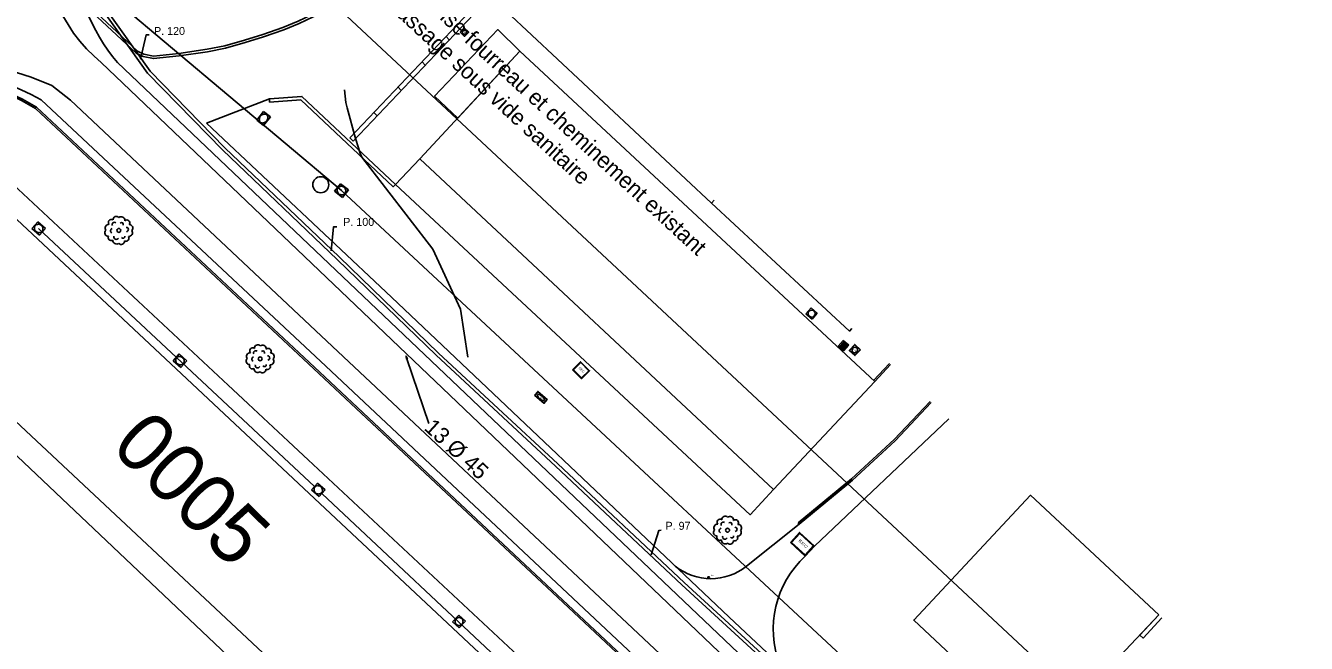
# Model space of a CAD drawing. Extents: x 343997 to 344255, y 298512 to 298767.
# Drawn here: x 344175.3 to 344255.3, y 298632.9 to 298671.5 of the extents above; entities that cross this region are included whole.
import ezdxf

# ---------------------------------------------------------------- set-up
doc = ezdxf.new("R2010")
doc.units = 0
for name, color, linetype in [('Commentaires', 7, 'Continuous'), ('Default', 7, 'Continuous'), ('DH_CADRE -CARTOUCHE', 7, 'Continuous'), ('DH_CADRE-CARTOUCHE', 7, 'Continuous'), ('DH_CADRE-CARTOUCHE-NORD', 7, 'Continuous'), ('DH_TEXTE', 7, 'Continuous'), ('DIR-Projet VRD1', 7, 'Continuous'), ('EL-FOURR', 7, 'Continuous'), ('GO_DALLE', 7, 'Continuous'), ('GO_MUR', 7, 'Continuous'), ('MT-DONNEE', 7, 'Continuous'), ('O-Projet New VRD', 7, 'Continuous'), ('PC_REBAR', 7, 'Continuous'), ('PS_MID', 7, 'Continuous'), ('PS_OBJECT', 7, 'Continuous'), ('PS_PLATE', 7, 'Continuous'), ('RES_EAU', 7, 'Continuous'), ('RES_EAU PLUVIALE', 7, 'Continuous'), ('RES_ELECTRICITE', 7, 'Continuous'), ('RES_MOYENNE TENSION', 7, 'Continuous')]:
    doc.layers.add(name, color=color, linetype=linetype)

# ---------------------------------------------------------------- blocks, each defined once
blk = doc.blocks.new('REG_INC')
at = {"layer": 'Default'}
for p, q in [((0, 0.1), (0.1, 0.1)), ((0, 0), (0, 0.1)), ((0.1, 0), (0, 0)), ((0.1, 0.1), (0.1, 0))]:
    blk.add_line(p, q, dxfattribs=at)
for start, end in [(135.0055, 180.0055), (180.0066, 225.0066), (90.0058, 135.0058), (225.0069, 270.0069), (45.0069, 90.0069), (270.0058, 315.0058), (0.0066, 45.0066), (315.0055, 0.0055)]:
    blk.add_arc((0.05, 0.05), 0.044, start, end, dxfattribs=at)
blk = doc.blocks.new('R5')
at = {"layer": 'Default'}
for p, q in [((0, 0.1), (0, 0)), ((0.1, 0.1), (0, 0.1)), ((0.02, 0.1), (0.02, 0)), ((0.04, 0.1), (0.04, 0)), ((0.06, 0.1), (0.06, 0)), ((0.08, 0.1), (0.08, 0)), ((0.1, 0), (0.1, 0.1)), ((0, 0), (0.1, 0)), ((0.06, 0), (0.06, 0))]:
    blk.add_line(p, q, dxfattribs=at)
blk = doc.blocks.new('RES_EAU')
at = {"layer": 'RES_EAU'}
for points in [[(0, 0), (0, 0.1), (0.1, 0.1), (0.1, 0)], [(0.003, 0.003), (0.003, 0.097), (0.097, 0.097), (0.097, 0.003)]]:
    blk.add_lwpolyline(points, close=True, dxfattribs=at)
blk.add_circle((0.05, 0.05), 0.035, dxfattribs=at)
blk.add_text('AEP', height=0.02, dxfattribs=at).set_placement((0.022, 0.045))
blk = doc.blocks.new('RES_ELECTRICITE')
at = {"layer": 'RES_ELECTRICITE'}
for points in [[(0, 0), (0, 0.1), (0.1, 0.1), (0.1, 0)], [(0.005, 0.005), (0.005, 0.095), (0.095, 0.095), (0.095, 0.005)]]:
    blk.add_lwpolyline(points, close=True, dxfattribs=at)
blk.add_text('EEC', height=0.02, dxfattribs=at).set_placement((0.0237, 0.046))
blk = doc.blocks.new('BC2')
at = {"layer": 'Default'}
blk.add_line((-0.011, -0.011), (0.011, 0.011), dxfattribs=at)
blk.add_circle((0, 0), 0.015, dxfattribs=at)
blk.add_text('EAU', height=0.0227, dxfattribs=at).set_placement((0.017, 0.026))
blk = doc.blocks.new('ARB1')
at = {"layer": 'Default'}
blk.add_circle((0, 0), 0.0122, dxfattribs=at)
for centre, radius, start, end in [((-0.0153, 0.0664), 0.0211, 43.69255, 183.5969), ((0.0139, 0.0613), 0.0241, 358.45835, 125.19284), ((-0.0613, 0.0139), 0.0241, 88.45835, 215.19284), ((-0.0471, 0.0503), 0.0183, 53.95544, 222.20655), ((-0.0373, -0.0024), 0.0149, 103.70924, 242.34652), ((-0.0276, 0.037), 0.0134, 52.43963, 209.54959), ((0.0164, 0.038), 0.0112, 330.58954, 133.71274), ((0.0501, 0.0468), 0.0183, 325.14445, 131.01755), ((0.0458, 0.0052), 0.0137, 276.62143, 88.96702), ((0.0613, -0.0139), 0.0241, 268.45835, 35.19284), ((0.0664, 0.0153), 0.0211, 313.69255, 93.5969), ((-0.0664, -0.0153), 0.0211, 133.69255, 273.5969), ((-0.0478, -0.0443), 0.019, 155.22426, 300.93774), ((-0.0139, -0.0613), 0.0241, 178.45835, 305.19284), ((-0.0163, -0.042), 0.0148, 159.53711, 338.16632), ((0.0153, -0.0664), 0.0211, 223.69255, 3.5969), ((0.0271, -0.038), 0.0112, 210.58954, 13.71274), ((0.0448, -0.0483), 0.0188, 243.13234, 33.02965)]:
    blk.add_arc(centre, radius, start, end, dxfattribs=at)

msp = doc.modelspace()

# ---------------------------------------------------------------- linework, layer by layer
at = {"layer": 'DH_CADRE -CARTOUCHE'}
for points in [[(343997.309, 298660.673), (344147.183, 298520.807), (344245.09, 298625.72), (344095.215, 298765.586)], [(344246.085, 298634.723), (344238.071, 298642.203), (344230.773, 298634.4), (344238.733, 298626.952)]]:
    msp.add_lwpolyline(points, close=True, dxfattribs=at)
at = {"layer": 'DH_CADRE-CARTOUCHE'}
for p, q in [((344229.255, 298650.429), (344228.265, 298649.367)), ((344229.328, 298650.361), (344228.339, 298649.299))]:
    msp.add_line(p, q, dxfattribs=at)
for points in [[(344188, 298688.93), (344187.902, 298688.824), (344177.441, 298677.433), (344176.96, 298676.824), (344176.719, 298676.211), (344176.783, 298675.437), (344177.049, 298674.626), (344182.208, 298669.797), (344182.64, 298669.601), (344183.285, 298669.47), (344184.88, 298669.638), (344186.656, 298669.899), (344187.783, 298670.119), (344189.007, 298670.475), (344190.164, 298670.82), (344191.42, 298671.271), (344192.391, 298671.666), (344193.259, 298672.085), (344195.097, 298672.911), (344197.862, 298674.128), (344198.708, 298674.569), (344199.685, 298675.181), (344198.697, 298676.128)], [(344188.109, 298688.828), (344188.012, 298688.722), (344177.555, 298677.336), (344177.092, 298676.749), (344176.872, 298676.188), (344176.931, 298675.467), (344177.18, 298674.709), (344182.292, 298669.924), (344182.687, 298669.745), (344183.293, 298669.621), (344184.862, 298669.787), (344186.631, 298670.046), (344187.747, 298670.264), (344188.964, 298670.619), (344190.117, 298670.962), (344191.366, 298671.411), (344192.331, 298671.803), (344193.196, 298672.221), (344195.036, 298673.048), (344197.797, 298674.263), (344198.633, 298674.699), (344199.442, 298675.206), (344198.593, 298676.019), (344198.697, 298676.128)], [(344173.884, 298668.877), (344175.641, 298668.318), (344176.928, 298667.79), (344178.107, 298666.872), (344194.798, 298651.17), (344217.989, 298629.411), (344240.944, 298607.781), (344244.256, 298604.654)], [(344186.596, 298665.445), (344190.525, 298666.955)], [(344253.72, 298623.882), (344254.601, 298622.951), (344255.115, 298621.851), (344255.304, 298620.858), (344255.289, 298620.014), (344254.937, 298619.35), (344253.379, 298617.242), (344250.056, 298613.162), (344249.016, 298611.996), (344247.858, 298610.985), (344246.303, 298610.451), (344244.928, 298610.512), (344219.242, 298634.584), (344198.152, 298654.571), (344186.596, 298665.445)], [(344223.547, 298640.473), (344226.888, 298643.225), (344229.555, 298645.674), (344231.797, 298648.057)], [(344223.61, 298640.396), (344226.953, 298643.149), (344229.625, 298645.603), (344231.87, 298647.989)], [(344224.003, 298638.398), (344224.585, 298639.016), (344232.966, 298646.967)], [(344223.61, 298640.396), (344220.335, 298637.772)], [(344223.547, 298640.473), (344223.61, 298640.396)]]:
    msp.add_lwpolyline(points, dxfattribs=at)
for centre, radius, start, end in [((344218.106, 298640.554), 3.565, 231.25262, 308.69595), ((344228.199, 298633.832), 6.201, 132.57867, 200.9263)]:
    msp.add_arc(centre, radius, start, end, dxfattribs=at)
at = {"layer": 'DH_CADRE-CARTOUCHE-NORD'}
for p, q in [((344176.111, 298658.859), (344193.341, 298642.746)), ((344193.828, 298642.286), (344215.714, 298621.751))]:
    msp.add_line(p, q, dxfattribs=at)
msp.add_lwpolyline([(344237.935, 298621.298), (344195.027, 298661.228), (344177.442, 298676.027), (344168.974, 298681.087)], dxfattribs=at)
at = {"layer": 'DIR-Projet VRD1'}
msp.add_line((344180.02, 298669.219), (344245.896, 298606.412), dxfattribs=at)
msp.add_arc((344186.231, 298676.743), 9.758, 171.07144, 230.59024, dxfattribs=at)
at = {"layer": 'EL-FOURR'}
for points in [[(344246.89, 298607.477), (344237.55, 298616.33), (344230.72, 298622.88), (344224.44, 298629.13), (344216.3, 298636.61), (344208.4, 298644.02), (344200.94, 298650.94), (344194.75, 298656.93), (344187.61, 298663.75), (344182.92, 298668.55), (344179.08, 298673.97)], [(344179.26, 298674.06), (344183.08, 298668.68), (344187.75, 298663.89), (344194.89, 298657.08), (344201.08, 298651.08), (344208.54, 298644.17), (344216.43, 298636.76), (344224.58, 298629.27), (344230.85, 298623.02), (344237.69, 298616.48), (344247.03, 298607.627)]]:
    msp.add_lwpolyline(points, dxfattribs=at)
at = {"layer": 'GO_DALLE'}
for points in [[(344173.637, 298593.851), (344172.292, 298595.161), (344185.567, 298608.8), (344198.259, 298622.397), (344163.217, 298655.561), (344163.898, 298656.291), (344171.693, 298664.218), (344209.192, 298629.258), (344201.744, 298621.299), (344205.95, 298617.379), (344203.771, 298607.721), (344197.46, 298609.156), (344192.341, 298613.899), (344190.988, 298612.393), (344196.963, 298606.8), (344195.985, 298605.701)], [(344246.272, 298634.549), (344245.098, 298633.284), (344244.9, 298633.471), (344246.085, 298634.723)]]:
    msp.add_lwpolyline(points, dxfattribs=at)
msp.add_lwpolyline([(344199.92, 298663.204), (344198.399, 298661.611), (344220.56, 298640.98), (344222.021, 298642.559)], close=True, dxfattribs=at)
at = {"layer": 'GO_MUR'}
for points in [[(344162.931, 298666.015), (344158.413, 298661.325), (344158.342, 298661.39), (344163.216, 298666.766), (344163.731, 298667.308), (344164.688, 298668.072), (344165.676, 298668.545), (344166.447, 298668.825), (344167.222, 298669.059), (344168.509, 298669.289), (344169.751, 298669.392), (344170.251, 298669.414), (344170.803, 298669.375), (344172.06, 298669.227), (344173.884, 298668.877), (344175.641, 298668.318), (344176.928, 298667.79), (344178.107, 298666.872), (344194.798, 298651.17), (344217.989, 298629.411), (344217.037, 298628.671)], [(344175.978, 298666.428), (344193.686, 298649.877), (344216.254, 298628.72), (344216.185, 298628.648), (344193.618, 298649.804), (344175.917, 298666.349)], [(344217.037, 298628.671), (344194.049, 298650.256), (344176.274, 298666.89)]]:
    msp.add_lwpolyline(points, dxfattribs=at)
msp.add_lwpolyline([(344190.525, 298666.955), (344192.555, 298667.101), (344198.399, 298661.611), (344198.262, 298661.465), (344192.482, 298666.895), (344190.539, 298666.755)], close=True, dxfattribs=at)
msp.add_circle((344193.735, 298661.592), 0.5, dxfattribs=at)
for centre, radius, start, end in [((344169.681, 298656.377), 11.761, 57.97822, 83.98576), ((344169.681, 298656.377), 11.861, 57.93142, 83.98962), ((344168.988, 298653.784), 14.995, 60.9281, 82.46983)]:
    msp.add_arc(centre, radius, start, end, dxfattribs=at)
at = {"layer": 'MT-DONNEE'}
for points in [[(344182.47, 298669.43), (344182.82, 298670.95), (344183.02, 298670.95)], [(344194.39, 298657.46), (344194.54, 298658.97), (344194.74, 298658.97)], [(344214.37, 298638.48), (344214.85, 298639.99), (344215, 298640.02)]]:
    msp.add_lwpolyline(points, dxfattribs=at)
at = {"layer": 'O-Projet New VRD'}
msp.add_lwpolyline([(344199.091, 298650.705), (344199.061, 298650.885), (344199.148, 298650.724)], close=True, dxfattribs=at)
msp.add_lwpolyline([(344199.119, 298650.715), (344200.488, 298646.683)], dxfattribs=at)
at = {"layer": 'PS_MID'}
msp.add_lwpolyline([(344202.301, 298665.744), (344200.842, 298667.111), (344204.795, 298671.279), (344206.167, 298669.932)], close=True, dxfattribs=at)
msp.add_lwpolyline([(344226.917, 298652.611), (344226.766, 298652.449), (344218.145, 298660.448)], dxfattribs=at)
at = {"layer": 'PS_OBJECT'}
msp.add_lwpolyline([(344202.925, 298650.83), (344202.457, 298653.824), (344200.73, 298657.577), (344196.307, 298663.307), (344196.174, 298663.613), (344196.088, 298663.905), (344195.908, 298664.48), (344195.376, 298666.385), (344195.306, 298666.724), (344195.213, 298667.526)], dxfattribs=at)
at = {"layer": 'PS_PLATE'}
msp.add_lwpolyline([(344218.319, 298660.635), (344218.145, 298660.448), (344195.697, 298681.448), (344195.845, 298681.608)], dxfattribs=at)
for points in [[(344206.167, 298669.932), (344199.92, 298663.204), (344222.021, 298642.559), (344228.339, 298649.299)], [(344200.65, 298622.487), (344165.426, 298655.454), (344171.721, 298662.233), (344206.962, 298629.231)]]:
    msp.add_lwpolyline(points, close=True, dxfattribs=at)
at = {"layer": 'RES_MOYENNE TENSION'}
msp.add_line((344181.027, 298669.218), (344246.474, 298607.032), dxfattribs=at)
msp.add_arc((344190.578, 298677.102), 12.385, 183.67072, 219.54085, dxfattribs=at)

# ---------------------------------------------------------------- block references
at = {"layer": 'PC_REBAR', "xscale": 10, "yscale": 10}
for p in [(344181.12, 298658.739), (344189.95, 298650.719), (344219.146, 298640.016)]:
    msp.add_blockref('ARB1', p, dxfattribs=at)
at = {"layer": 'RES_EAU'}
for p, xscale, yscale, rotation in [((344202.442, 298671.11), 3.8109408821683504, 3.769934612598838, -42.97545000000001), ((344227.444, 298651.287), 4.796261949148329, 5.059180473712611, 136.82717999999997), ((344207.089, 298648.441), 3.1404174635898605, -7.73488420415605, 49.186619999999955)]:
    msp.add_blockref('RES_EAU', p, dxfattribs=dict(at, xscale=xscale, yscale=yscale, rotation=rotation))
at = {"layer": 'RES_EAU', "xscale": 4, "yscale": 4}
msp.add_blockref('BC2', (344217.964, 298637.053), dxfattribs=at)
at = {"layer": 'RES_EAU PLUVIALE'}
for name, p, xscale, yscale, rotation in [('R5', (344195.759, 298664.32), 109.04369023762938, 2.7718751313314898, 46.491209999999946), ('REG_INC', (344190.157, 298666.166), 5.44789682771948, -6.934859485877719, -37.86570000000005), ('REG_INC', (344195.459, 298661.265), 6.254069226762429, 6.004786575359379, 141.24761999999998), ('REG_INC', (344176.063, 298659.282), 5.70230917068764, 6.312126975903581, -131.48361), ('REG_INC', (344224.044, 298653.53), 4.9360458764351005, -5.065070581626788, 48.236309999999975), ('R5', (344226.723, 298651.581), 4.515576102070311, 4.84988598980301, 140.06735999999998), ('REG_INC', (344184.895, 298651.021), 5.70230917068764, 6.312126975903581, -131.48361), ('REG_INC', (344193.53, 298642.959), 5.70230917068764, 6.312126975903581, -131.48361), ('REG_INC', (344202.369, 298634.717), 5.772372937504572, 5.6266999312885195, -133.64937)]:
    msp.add_blockref(name, p, dxfattribs=dict(at, xscale=xscale, yscale=yscale, rotation=rotation))
at = {"layer": 'RES_ELECTRICITE'}
for p, xscale, yscale, rotation in [((344209.47, 298650.035), 7.908739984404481, 7.0593969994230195, -45.06567324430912), ((344223.069, 298639.255), 12.671312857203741, 8.49345270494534, -42.500046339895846)]:
    msp.add_blockref('RES_ELECTRICITE', p, dxfattribs=dict(at, xscale=xscale, yscale=yscale, rotation=rotation))

# ---------------------------------------------------------------- texts
at = {"layer": 'Commentaires'}
for s, p in [('Reprise fourreau et cheminement existant', (344198.986, 298673.927)), ('passage sous vide sanitaire', (344197.869, 298672.689))]:
    msp.add_text(s, height=1.00027, rotation=317.36723, dxfattribs=at).set_placement(p)
at = {"layer": 'DH_TEXTE'}
msp.add_text('0005', height=3.662, rotation=315.36651, dxfattribs=at).set_placement((344180.527, 298645.151))
at = {"layer": 'MT-DONNEE'}
for s, p in [('P. 120', (344183.32, 298670.94)), ('P. 100', (344195.14, 298659.02)), ('P. 97', (344215.27, 298640.04))]:
    msp.add_text(s, height=0.5, dxfattribs=at).set_placement(p)
at = {"layer": 'O-Projet New VRD'}
msp.add_text('13 Ø 45', height=1.0003, rotation=317.36723, dxfattribs=at).set_placement((344200.137, 298646.331))

doc.saveas('drawing.dxf')
